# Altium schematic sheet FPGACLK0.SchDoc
size D; PageSetup: Record=PageOptions|CenterHorizontal=True|CenterVertical=True|PrintScale=1.12|XCorrection=1.00|YCorrection=1.00|PrintKind=0|BorderSize=5000000|LeftOffset=0|BottomOffset=0|Orientation=2|PaperLength=1000|PaperWidth=1000|Scale=100|PaperSource=7|PrintQuality=-4|MediaType=1|DitherType=10|PaperKind=Letter|PrintScaleMode=1
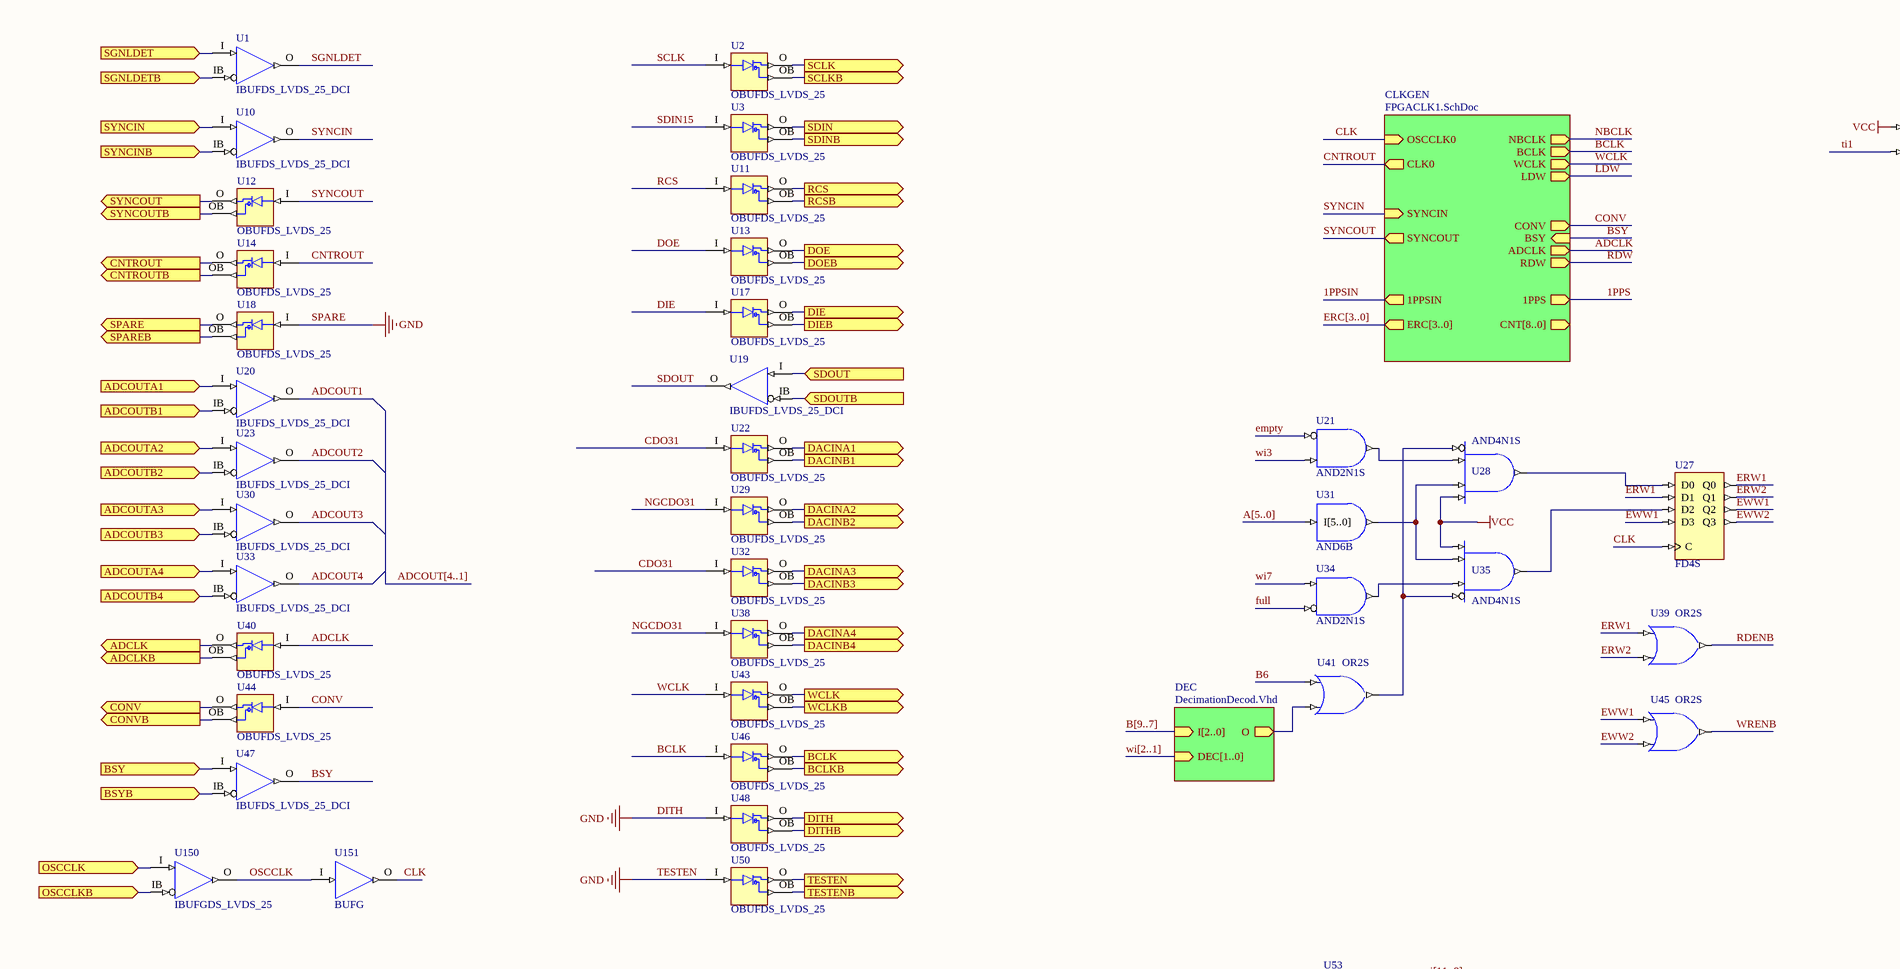
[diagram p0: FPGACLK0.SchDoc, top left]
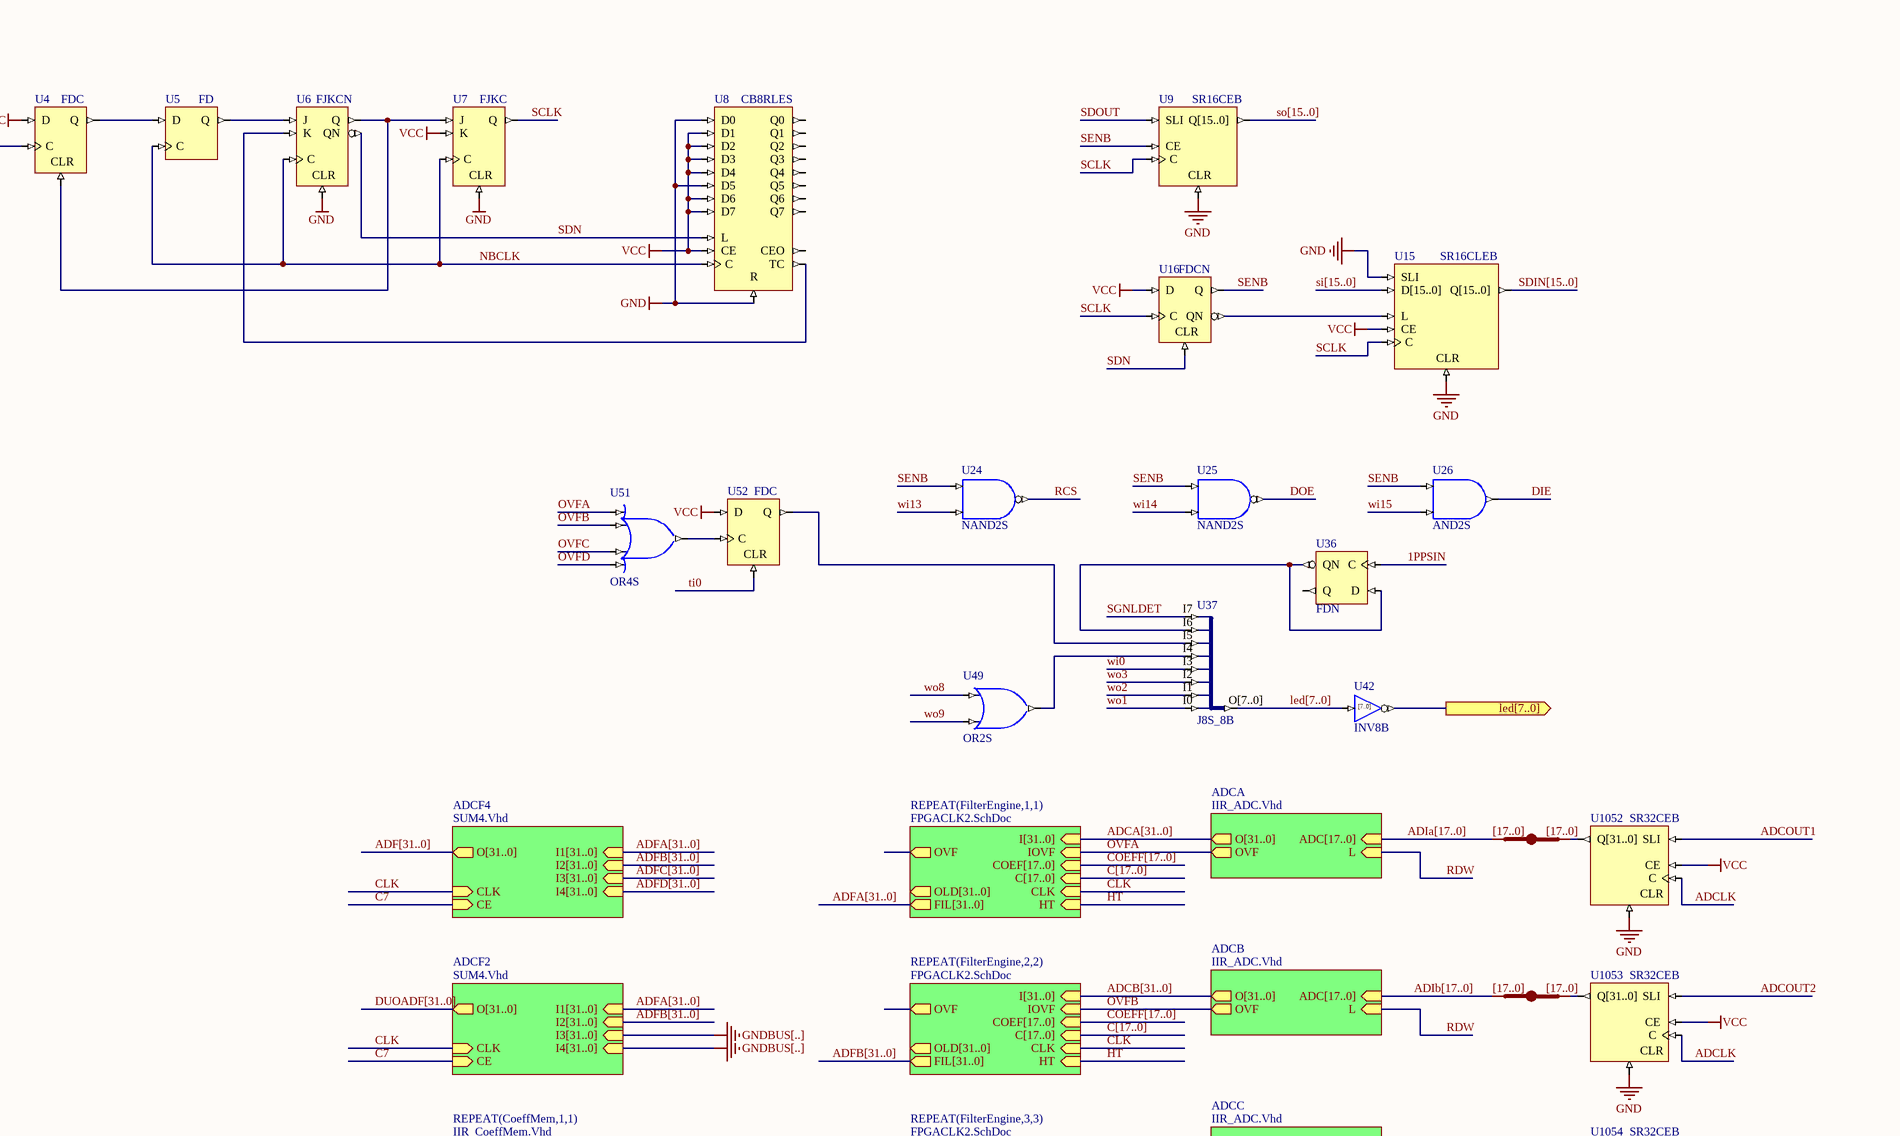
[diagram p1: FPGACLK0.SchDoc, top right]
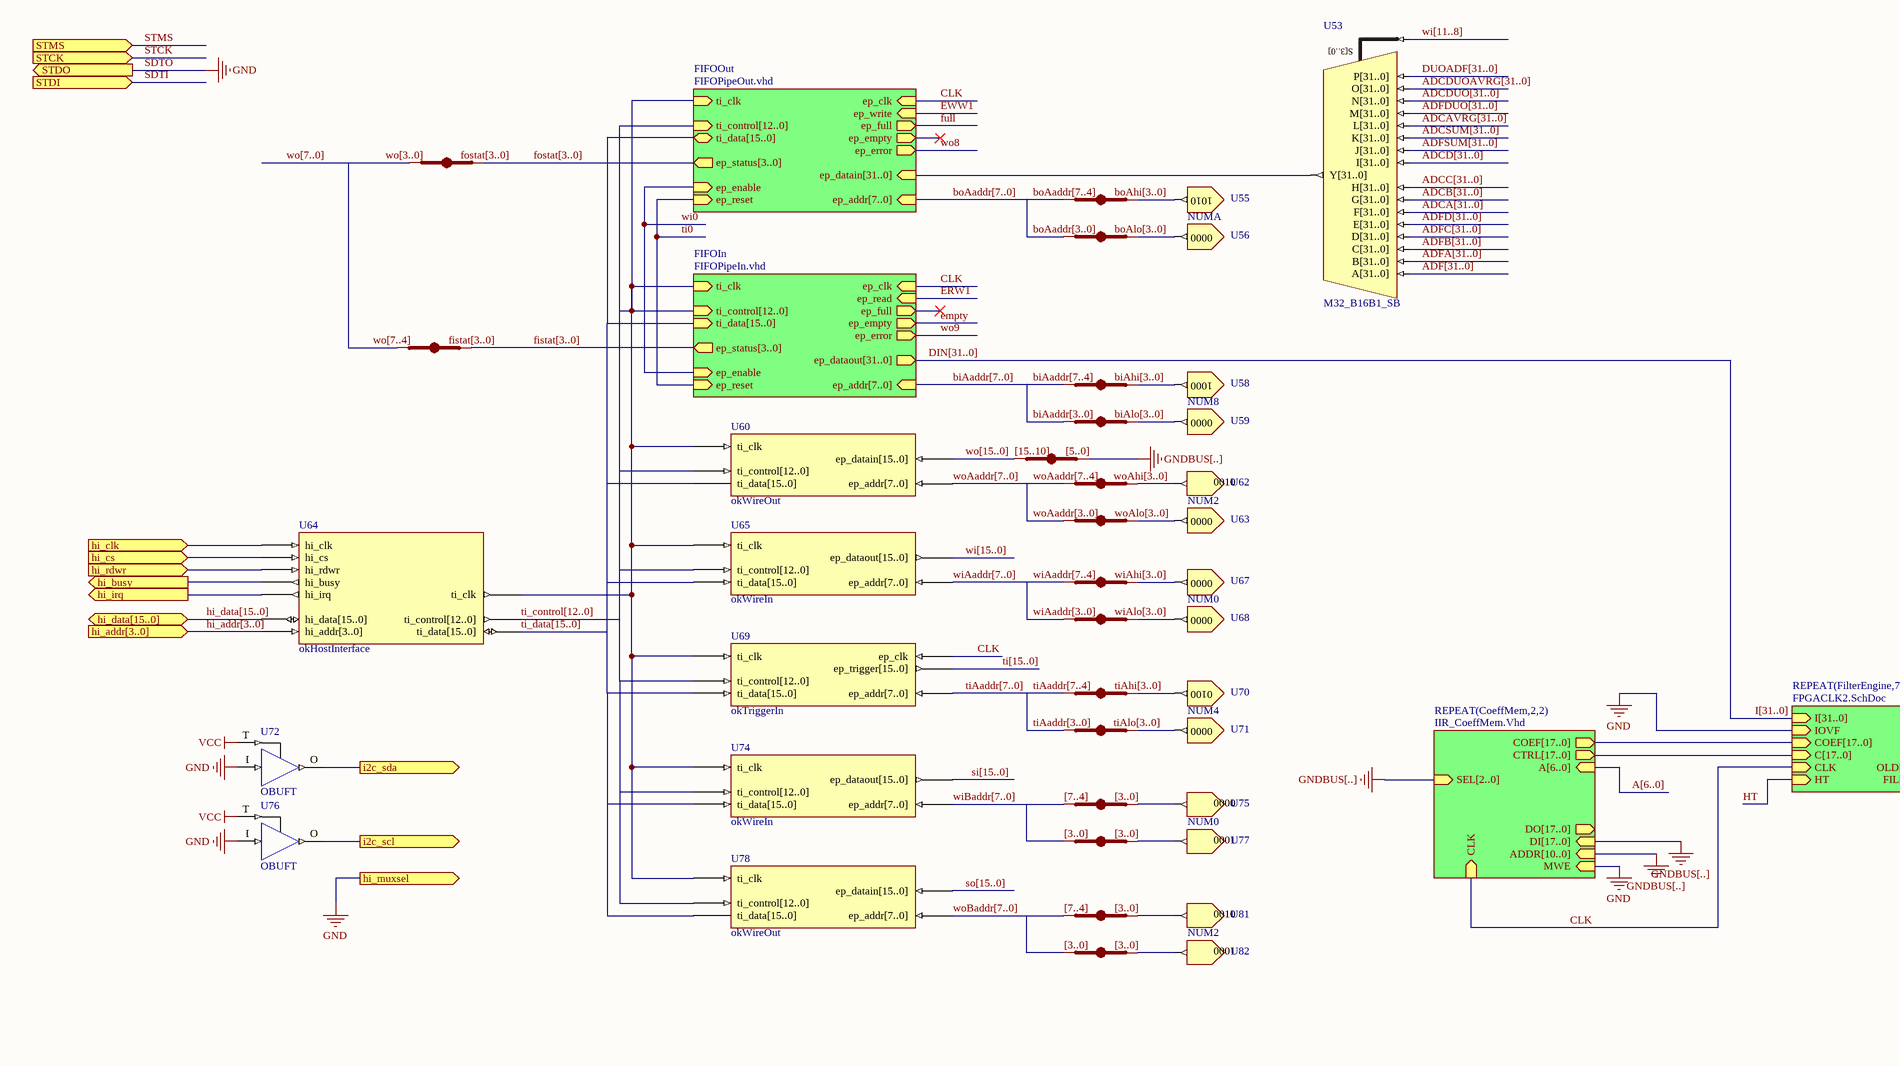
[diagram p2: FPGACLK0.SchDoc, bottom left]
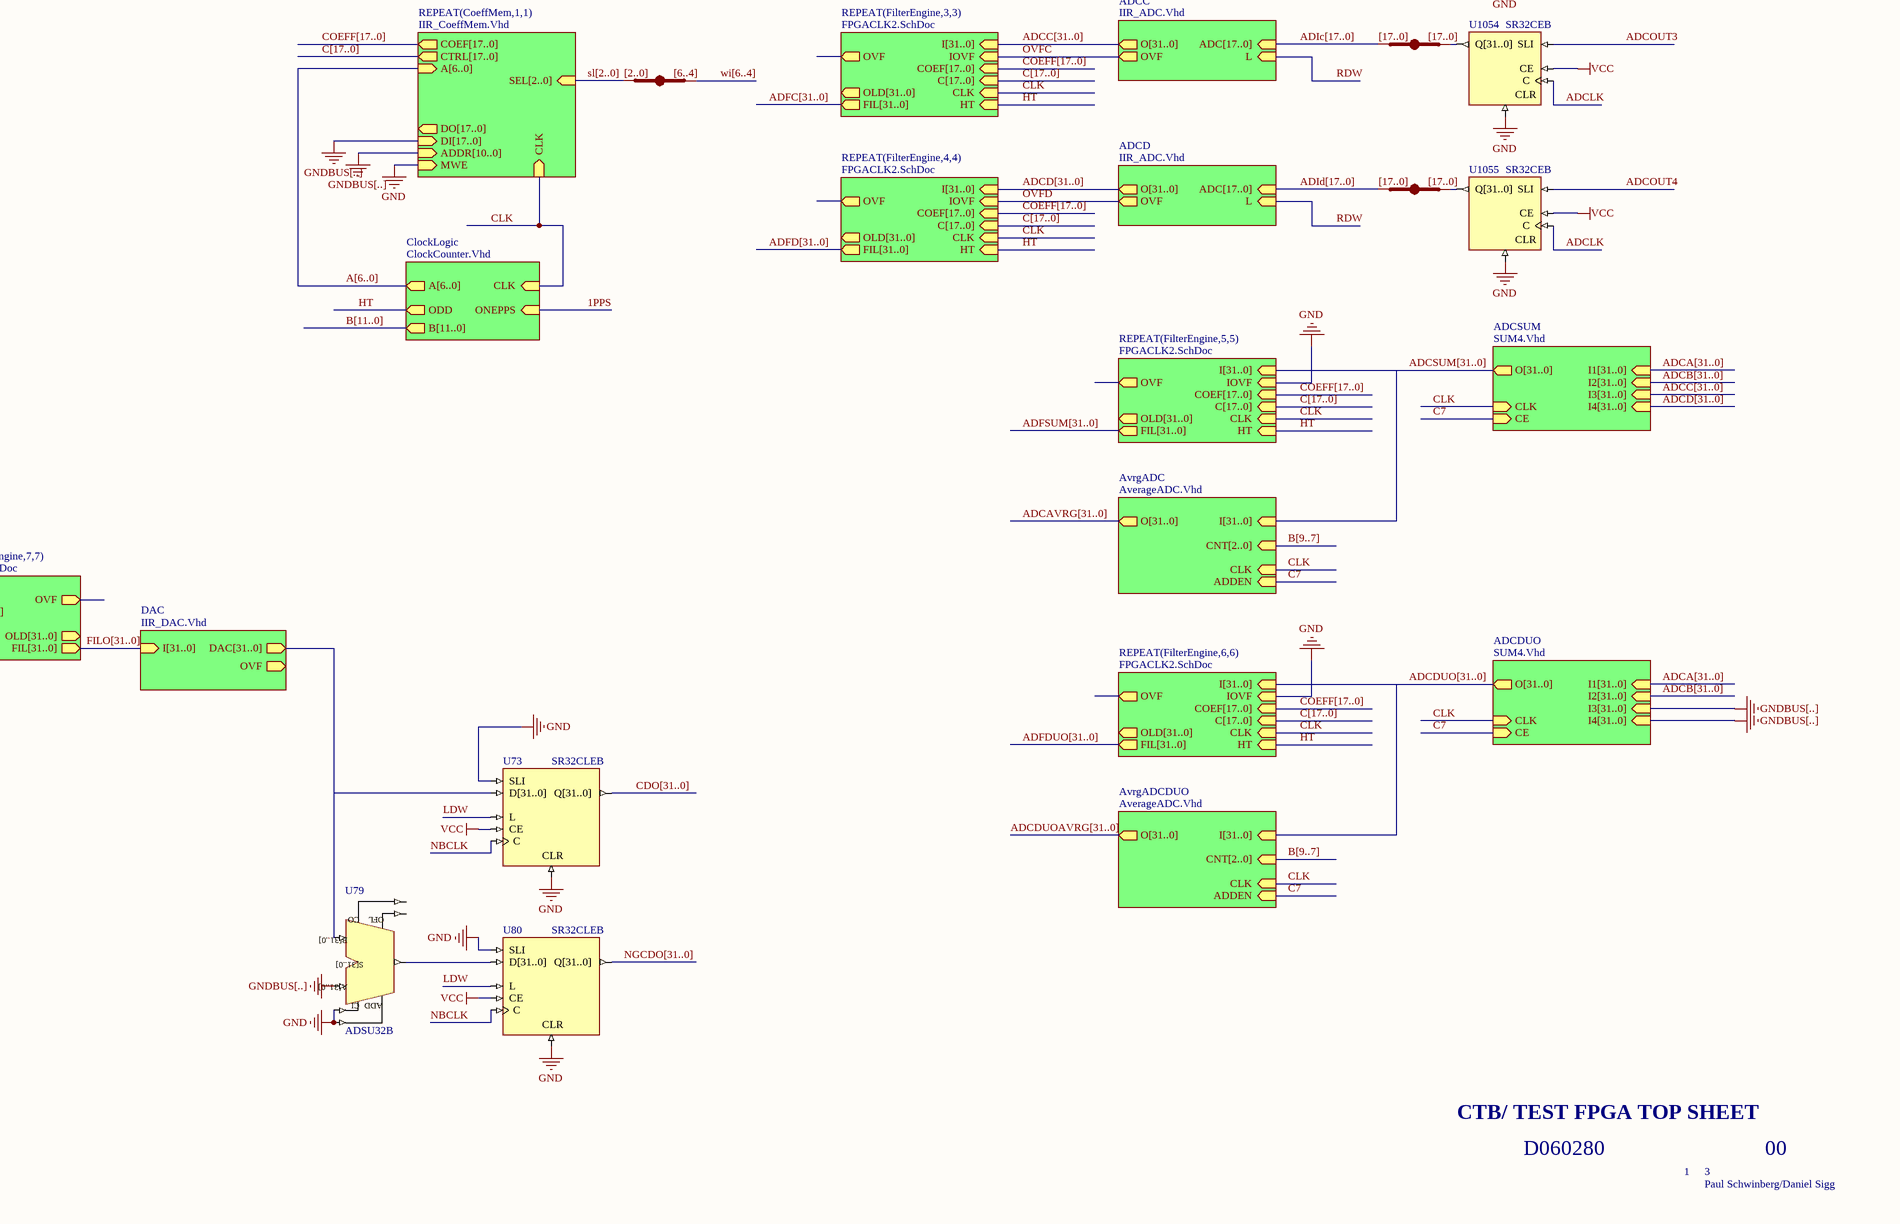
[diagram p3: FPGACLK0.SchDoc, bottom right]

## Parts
(Parts that share a designator on the sheet are numbered #1, #2 ... from top to bottom, then left to right.)
JB_C1#1  IndexA: [17..0]  (hidden comment: JB)
JB_C1#2  IndexA: [17..0]  (hidden comment: JB)
JB_C1#3  IndexA: [17..0]  (hidden comment: JB)
JB_C1#4  IndexA: [17..0]  (hidden comment: JB)
JB_C3  IndexA: wo[3..0]  IndexB: fostat[3..0]  (hidden comment: JB)
JB_C4  IndexA: boAaddr[7..4]  IndexB: boAhi[3..0]  (hidden comment: JB)
JB_C6  IndexA: [2..0]  IndexB: [6..4]  (hidden comment: JB)
JB_C7  IndexA: boAaddr[3..0]  IndexB: boAlo[3..0]  (hidden comment: JB)
JB_C9  IndexA: wo[7..4]  IndexB: fistat[3..0]  (hidden comment: JB)
JB_C10  IndexA: biAaddr[7..4]  IndexB: biAhi[3..0]  (hidden comment: JB)
JB_C11  IndexA: biAaddr[3..0]  IndexB: biAlo[3..0]  (hidden comment: JB)
JB_C12  IndexA: [15..10]  IndexB: [5..0]  (hidden comment: JB)
JB_C13  IndexA: woAaddr[7..4]  IndexB: woAhi[3..0]  (hidden comment: JB)
JB_C15  IndexA: woAaddr[3..0]  IndexB: woAlo[3..0]  (hidden comment: JB)
JB_C16  IndexA: wiAaddr[7..4]  IndexB: wiAhi[3..0]  (hidden comment: JB)
JB_C18  IndexA: wiAaddr[3..0]  IndexB: wiAlo[3..0]  (hidden comment: JB)
JB_C19  IndexA: tiAaddr[7..4]  IndexB: tiAhi[3..0]  (hidden comment: JB)
JB_C20  IndexA: tiAaddr[3..0]  IndexB: tiAlo[3..0]  (hidden comment: JB)
JB_C21  IndexA: [7..4]  IndexB: [3..0]  (hidden comment: JB)
JB_C22  IndexA: [3..0]  (hidden comment: JB)
JB_C23  IndexA: [7..4]  IndexB: [3..0]  (hidden comment: JB)
JB_C24  IndexA: [3..0]  (hidden comment: JB)
U1  IBUFDS_LVDS_25_DCI
U2  OBUFDS_LVDS_25
U3  OBUFDS_LVDS_25
U4  FDC
U5  FD
U6  FJKCN
U7  FJKC
U8  CB8RLES
U9  SR16CEB
U10  IBUFDS_LVDS_25_DCI
U11  OBUFDS_LVDS_25
U12  OBUFDS_LVDS_25
U13  OBUFDS_LVDS_25
U14  OBUFDS_LVDS_25
U15  SR16CLEB
U16  FDCN
U17  OBUFDS_LVDS_25
U18  OBUFDS_LVDS_25
U19  IBUFDS_LVDS_25_DCI
U20  IBUFDS_LVDS_25_DCI
U21  AND2N1S
U22  OBUFDS_LVDS_25
U23  IBUFDS_LVDS_25_DCI
U24  NAND2S
U25  NAND2S
U26  AND2S
U27  FD4S
U28  AND4N1S
U29  OBUFDS_LVDS_25
U30  IBUFDS_LVDS_25_DCI
U31  AND6B
U32  OBUFDS_LVDS_25
U33  IBUFDS_LVDS_25_DCI
U34  AND2N1S
U35  AND4N1S
U36  FDN
U37  J8S_8B
U38  OBUFDS_LVDS_25
U39  OR2S
U40  OBUFDS_LVDS_25
U41  OR2S
U42  INV8B
U43  OBUFDS_LVDS_25
U44  OBUFDS_LVDS_25
U45  OR2S
U46  OBUFDS_LVDS_25
U47  IBUFDS_LVDS_25_DCI
U48  OBUFDS_LVDS_25
U49  OR2S
U50  OBUFDS_LVDS_25
U51  OR4S
U52  FDC
U53  M32_B16B1_SB
U55  NUMA
U56  NUM0  (value not drawn)
U58  NUM8
U59  NUM0  (value not drawn)
U60  okWireOut
U62  NUM2
U63  NUM0  (value not drawn)
U64  okHostInterface
U65  okWireIn
U67  NUM0
U68  NUM0  (value not drawn)
U69  okTriggerIn
U70  NUM4
U71  NUM0  (value not drawn)
U72  OBUFT
U73  SR32CLEB
U74  okWireIn
U75  NUM0
U76  OBUFT
U77  NUM1  (value not drawn)
U78  okWireOut
U79  ADSU32B
U80  SR32CLEB
U81  NUM2
U82  NUM1  (value not drawn)
U150  IBUFGDS_LVDS_25
U151  BUFG
U1052  SR32CEB
U1053  SR32CEB
U1054  SR32CEB
U1055  SR32CEB

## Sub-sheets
ADCA = IIR_ADC.Vhd: ADC[17..0] (in), O[31..0] (out), L (in), OVF (out)
ADCB = IIR_ADC.Vhd: ADC[17..0] (in), O[31..0] (out), L (in), OVF (out)
ADCC = IIR_ADC.Vhd: ADC[17..0] (in), O[31..0] (out), L (in), OVF (out)
ADCD = IIR_ADC.Vhd: ADC[17..0] (in), O[31..0] (out), L (in), OVF (out)
ADCDUO = SUM4.Vhd: I1[31..0] (in), O[31..0] (out), I2[31..0] (in), I3[31..0] (in), I4[31..0] (in), CLK (in), CE (in)
ADCF2 = SUM4.Vhd: I1[31..0] (in), O[31..0] (out), I2[31..0] (in), I3[31..0] (in), I4[31..0] (in), CLK (in), CE (in)
ADCF4 = SUM4.Vhd: I1[31..0] (in), O[31..0] (out), I2[31..0] (in), I3[31..0] (in), I4[31..0] (in), CLK (in), CE (in)
ADCSUM = SUM4.Vhd: I1[31..0] (in), O[31..0] (out), I2[31..0] (in), I3[31..0] (in), I4[31..0] (in), CLK (in), CE (in)
AvrgADC = AverageADC.Vhd: I[31..0] (in), O[31..0] (out), ADDEN (in), CNT[2..0] (in), CLK (in)
AvrgADCDUO = AverageADC.Vhd: I[31..0] (in), O[31..0] (out), ADDEN (in), CNT[2..0] (in), CLK (in)
CLKGEN = FPGACLK1.SchDoc: SYNCIN (in), OSCCLK0 (in), CLK0 (out), SYNCOUT (out), BCLK (out), WCLK (out), LDW (out), CONV (out), BSY (in), ADCLK (out), RDW (out), NBCLK (out), 1PPS (out), 1PPSIN (out), ERC[3..0] (out), CNT[8..0] (out)
ClockLogic = ClockCounter.Vhd: CLK (in), ONEPPS (in), A[6..0] (out), ODD (out), B[11..0] (out)
DAC = IIR_DAC.Vhd: I[31..0] (in), DAC[31..0] (out), OVF (out)
DEC = DecimationDecod.Vhd: I[2..0] (in), O (out), DEC[1..0] (in)
FIFOIn = FIFOPipeIn.vhd: ti_clk (in), ti_control[12..0] (in), ti_data[15..0] (in), ep_status[3..0] (out), ep_reset (in), ep_clk (in), ep_read (in), ep_full (out), ep_empty (out), ep_error (out), ep_addr[7..0] (in), ep_dataout[31..0] (out), ep_enable (in)
FIFOOut = FIFOPipeOut.vhd: ti_clk (in), ti_control[12..0] (in), ti_data[15..0] (bidir), ep_status[3..0] (out), ep_reset (in), ep_clk (in), ep_write (in), ep_full (out), ep_empty (out), ep_error (out), ep_addr[7..0] (in), ep_datain[31..0] (in), ep_enable (in)
REPEAT(CoeffMem,1,1) = IIR_CoeffMem.Vhd: CLK (in), A[6..0] (in), COEF[17..0] (out), CTRL[17..0] (out), SEL[2..0] (in), DI[17..0] (in), DO[17..0] (out), MWE (in), ADDR[10..0] (in)
REPEAT(CoeffMem,2,2) = IIR_CoeffMem.Vhd: CLK (in), A[6..0] (in), COEF[17..0] (out), CTRL[17..0] (out), SEL[2..0] (in), DI[17..0] (in), DO[17..0] (out), MWE (in), ADDR[10..0] (in)
REPEAT(FilterEngine,1,1) = FPGACLK2.SchDoc: CLK (in), FIL[31..0] (out), I[31..0] (in), C[17..0] (in), COEF[17..0] (in), HT (in), OLD[31..0] (out), OVF (out), IOVF (in)
REPEAT(FilterEngine,2,2) = FPGACLK2.SchDoc: CLK (in), FIL[31..0] (out), I[31..0] (in), C[17..0] (in), COEF[17..0] (in), HT (in), OLD[31..0] (out), OVF (out), IOVF (in)
REPEAT(FilterEngine,3,3) = FPGACLK2.SchDoc: CLK (in), FIL[31..0] (out), I[31..0] (in), C[17..0] (in), COEF[17..0] (in), HT (in), OLD[31..0] (out), OVF (out), IOVF (in)
REPEAT(FilterEngine,4,4) = FPGACLK2.SchDoc: CLK (in), FIL[31..0] (out), I[31..0] (in), C[17..0] (in), COEF[17..0] (in), HT (in), OLD[31..0] (out), OVF (out), IOVF (in)
REPEAT(FilterEngine,5,5) = FPGACLK2.SchDoc: CLK (in), FIL[31..0] (out), I[31..0] (in), C[17..0] (in), COEF[17..0] (in), HT (in), OLD[31..0] (out), OVF (out), IOVF (in)
REPEAT(FilterEngine,6,6) = FPGACLK2.SchDoc: CLK (in), FIL[31..0] (out), I[31..0] (in), C[17..0] (in), COEF[17..0] (in), HT (in), OLD[31..0] (out), OVF (out), IOVF (in)
REPEAT(FilterEngine,7,7) = FPGACLK2.SchDoc: CLK (in), FIL[31..0] (out), I[31..0] (in), C[17..0] (in), COEF[17..0] (in), HT (in), OLD[31..0] (out), OVF (out), IOVF (in)

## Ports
ADCLK (out), ADCLKB (out), ADCOUTA1 (in), ADCOUTA2 (in), ADCOUTA3 (in), ADCOUTA4 (in), ADCOUTB1 (in), ADCOUTB2 (in), ADCOUTB3 (in), ADCOUTB4 (in), BCLK (out), BCLKB (out), BSY (in), BSYB (in), CNTROUT (out), CNTROUTB (out), CONV (out), CONVB (out), DACINA1 (out), DACINA2 (out), DACINA3 (out), DACINA4 (out), DACINB1 (out), DACINB2 (out), DACINB3 (out), DACINB4 (out), DIE (out), DIEB (out), DITH (out), DITHB (out), DOE (out), DOEB (out), hi_addr[3..0] (in), hi_busy (out), hi_clk (in), hi_cs (in), hi_data[15..0] (bidir), hi_irq (out), hi_muxsel (out), hi_rdwr (in), i2c_scl (out), i2c_sda (out), led[7..0] (out), OSCCLK (in), OSCCLKB (in), RCS (out), RCSB (out), SCLK (out), SCLKB (out), SDIN (out), SDINB (out), SDOUT (in), SDOUTB (in), SGNLDET (in), SGNLDETB (in), SPARE (out), SPAREB (out), STCK (in), STDI (in), STDO (out), STMS (in), SYNCIN (in), SYNCINB (in), SYNCOUT (out), SYNCOUTB (out), TESTEN (out), TESTENB (out), WCLK (out), WCLKB (out)

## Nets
DITH: U6.CLR U7.CLR U8.D0 U8.D5 U8.R U9.CLR U15.CLR U15.SLI U18.I U48.I U50.I U72.I U73.CLR U73.SLI U76.I U79.ADD U79.CI U80.CLR U80.SLI U1052.CLR U1053.CLR U1054.CLR U1055.CLR ; port hi_muxsel, port STDO, sheet REPEAT(CoeffMem,1,1)/MWE, sheet REPEAT(FilterEngine,7,7)/IOVF, sheet REPEAT(CoeffMem,2,2)/MWE, sheet REPEAT(FilterEngine,5,5)/IOVF, sheet REPEAT(FilterEngine,6,6)/IOVF  [also labelled GND, SDTO, SPARE, TESTEN]
GNDBUS[..]: U79.A[31..0]
VCC: U4.D U7.K U8.CE U8.D1 U8.D2 U8.D3 U8.D4 U8.D6 U8.D7 U15.CE U16.D U28.I3 U35.I3 U52.D U72.T U73.CE U76.T U80.CE U1052.CE U1053.CE U1054.CE U1055.CE
1PPS: sheet ClockLogic/ONEPPS, sheet CLKGEN/1PPS
1PPSIN: U36.C ; sheet CLKGEN/1PPSIN
ADCLK: U40.O ; port ADCLK
ADCLK: U40.I U1052.C U1053.C U1054.C U1055.C ; sheet CLKGEN/ADCLK  [a separate net that carries the same name]
ADCLKB: U40.OB ; port ADCLKB
ADCOUT1: U20.O U1052.SLI
ADCOUT2: U23.O U1053.SLI
ADCOUT3: U30.O U1054.SLI
ADCOUT4: U33.O U1055.SLI
ADCOUTA1: U20.I ; port ADCOUTA1
ADCOUTA2: U23.I ; port ADCOUTA2
ADCOUTA3: U30.I ; port ADCOUTA3
ADCOUTA4: U33.I ; port ADCOUTA4
ADCOUTB1: U20.IB ; port ADCOUTB1
ADCOUTB2: U23.IB ; port ADCOUTB2
ADCOUTB3: U30.IB ; port ADCOUTB3
ADCOUTB4: U33.IB ; port ADCOUTB4
B6: U41.I0
BCLK: U46.O ; port BCLK
BCLK: U46.I ; sheet CLKGEN/BCLK  [a separate net that carries the same name]
BCLKB: U46.OB ; port BCLKB
BSY: U47.O ; sheet CLKGEN/BSY
BSY: U47.I ; port BSY  [a separate net that carries the same name]
BSYB: U47.IB ; port BSYB
C7: sheet ADCF2/CE, sheet AvrgADC/ADDEN, sheet ADCSUM/CE, sheet AvrgADCDUO/ADDEN, sheet ADCDUO/CE, sheet ADCF4/CE
CDO31: U22.I U32.I
CLK: U27.C U69.ep_clk U151.O ; sheet ClockLogic/CLK, sheet REPEAT(CoeffMem,1,1)/CLK, sheet REPEAT(FilterEngine,7,7)/CLK, sheet REPEAT(CoeffMem,2,2)/CLK, sheet CLKGEN/OSCCLK0, sheet REPEAT(FilterEngine,1,1)/CLK, sheet REPEAT(FilterEngine,2,2)/CLK, sheet REPEAT(FilterEngine,3,3)/CLK, sheet REPEAT(FilterEngine,4,4)/CLK, sheet ADCF2/CLK, sheet AvrgADC/CLK, sheet ADCSUM/CLK, sheet REPEAT(FilterEngine,5,5)/CLK, sheet FIFOIn/ep_clk, sheet FIFOOut/ep_clk, sheet AvrgADCDUO/CLK, sheet ADCDUO/CLK, sheet REPEAT(FilterEngine,6,6)/CLK, sheet ADCF4/CLK
CNTROUT: U14.O ; port CNTROUT
CNTROUT: U14.I ; sheet CLKGEN/CLK0  [a separate net that carries the same name]
CNTROUTB: U14.OB ; port CNTROUTB
CONV: U44.O ; port CONV
CONV: U44.I ; sheet CLKGEN/CONV  [a separate net that carries the same name]
CONVB: U44.OB ; port CONVB
DACINA1: U22.O ; port DACINA1
DACINA2: U29.O ; port DACINA2
DACINA3: U32.O ; port DACINA3
DACINA4: U38.O ; port DACINA4
DACINB1: U22.OB ; port DACINB1
DACINB2: U29.OB ; port DACINB2
DACINB3: U32.OB ; port DACINB3
DACINB4: U38.OB ; port DACINB4
DIE: U17.O ; port DIE
DIE: U17.I U26.O  [a separate net that carries the same name]
DIEB: U17.OB ; port DIEB
DITH: U48.O ; port DITH  [a separate net that carries the same name]
DITHB: U48.OB ; port DITHB
DOE: U13.O ; port DOE
DOE: U13.I U25.O  [a separate net that carries the same name]
DOEB: U13.OB ; port DOEB
empty: U21.I0 ; sheet FIFOIn/ep_empty
ERW1: U27.D1 U27.Q0 U39.I0 ; sheet FIFOIn/ep_read
ERW2: U27.Q1 U39.I1
EWW1: U27.D3 U27.Q2 U45.I0 ; sheet FIFOOut/ep_write
EWW2: U27.Q3 U45.I1
full: U34.I0 ; sheet FIFOOut/ep_full
hi_busy: U64.hi_busy ; port hi_busy
hi_clk: U64.hi_clk ; port hi_clk
hi_cs: U64.hi_cs ; port hi_cs
hi_irq: U64.hi_irq ; port hi_irq
hi_rdwr: U64.hi_rdwr ; port hi_rdwr
HT: sheet ClockLogic/ODD, sheet REPEAT(FilterEngine,7,7)/HT, sheet REPEAT(FilterEngine,1,1)/HT, sheet REPEAT(FilterEngine,2,2)/HT, sheet REPEAT(FilterEngine,3,3)/HT, sheet REPEAT(FilterEngine,4,4)/HT, sheet REPEAT(FilterEngine,5,5)/HT, sheet REPEAT(FilterEngine,6,6)/HT
i2c_scl: U76.O ; port i2c_scl
i2c_sda: U72.O ; port i2c_sda
LDW: U73.L U80.L ; sheet CLKGEN/LDW
NBCLK: U5.C U6.C U7.C U8.C U73.C U80.C ; sheet CLKGEN/NBCLK
NGCDO31: U29.I U38.I
OSCCLK: U150.O U151.I
OSCCLK: U150.I ; port OSCCLK  [a separate net that carries the same name]
OSCCLKB: U150.IB ; port OSCCLKB
OVFA: U51.I0 ; sheet ADCA/OVF, sheet REPEAT(FilterEngine,1,1)/IOVF
OVFB: U51.I1 ; sheet ADCB/OVF, sheet REPEAT(FilterEngine,2,2)/IOVF
OVFC: U51.I2 ; sheet ADCC/OVF, sheet REPEAT(FilterEngine,3,3)/IOVF
OVFD: U51.I3 ; sheet ADCD/OVF, sheet REPEAT(FilterEngine,4,4)/IOVF
RCS: U11.O ; port RCS
RCS: U11.I U24.O  [a separate net that carries the same name]
RCSB: U11.OB ; port RCSB
RDENB: U39.O
RDW: sheet CLKGEN/RDW, sheet ADCC/L, sheet ADCD/L, sheet ADCB/L, sheet ADCA/L
SCLK: U2.O ; port SCLK
SCLK: U2.I U7.Q U9.C U15.C U16.C  [a separate net that carries the same name]
SCLKB: U2.OB ; port SCLKB
SDIN: U3.O ; port SDIN
SDIN15: U3.I
SDINB: U3.OB ; port SDINB
SDN: U6.QN U8.L U16.CLR
SDOUT: U9.SLI U19.O
SDOUT: U19.I ; port SDOUT  [a separate net that carries the same name]
SDOUTB: U19.IB ; port SDOUTB
SENB: U9.CE U16.Q U24.I0 U25.I0 U26.I0
SGNLDET: U1.O U37.I7
SGNLDET: U1.I ; port SGNLDET  [a separate net that carries the same name]
SGNLDETB: U1.IB ; port SGNLDETB
SPARE: U18.O ; port SPARE
SPAREB: U18.OB ; port SPAREB
SYNCIN: U10.O ; sheet CLKGEN/SYNCIN
SYNCIN: U10.I ; port SYNCIN  [a separate net that carries the same name]
SYNCINB: U10.IB ; port SYNCINB
SYNCOUT: U12.O ; port SYNCOUT
SYNCOUT: U12.I ; sheet CLKGEN/SYNCOUT  [a separate net that carries the same name]
SYNCOUTB: U12.OB ; port SYNCOUTB
TESTEN: U50.O ; port TESTEN
TESTENB: U50.OB ; port TESTENB
ti0: U52.CLR ; sheet FIFOIn/ep_reset, sheet FIFOOut/ep_reset
ti1: U4.C
WCLK: U43.O ; port WCLK
WCLK: U43.I ; sheet CLKGEN/WCLK  [a separate net that carries the same name]
WCLKB: U43.OB ; port WCLKB
wi0: U37.I3 ; sheet FIFOIn/ep_enable, sheet FIFOOut/ep_enable
wi3: U21.I1
wi7: U34.I1
wi13: U24.I1
wi14: U25.I1
wi15: U26.I1
wo1: U37.I0
wo2: U37.I1
wo3: U37.I2
wo8: U49.I0 ; sheet FIFOOut/ep_error
wo9: U49.I1 ; sheet FIFOIn/ep_error
WRENB: U45.O
NetU4_CLR: U4.CLR U6.Q U7.J
NetU4_Q: U4.Q U5.D
NetU5_Q: U5.Q U6.J
NetU6_K: U6.K U8.TC
NetU15_L: U15.L U16.QN
NetU21_O: U21.O U28.I1
NetU27_D0: U27.D0 U28.O
NetU27_D2: U27.D2 U35.O
NetU28_I0: U28.I0 U35.I0 U41.O
NetU28_I2: U28.I2 U31.O U35.I2
NetU34_O: U34.O U35.I1
NetU36_D: U36.D U36.QN U37.I6
NetU37_I4: U37.I4 U49.O
NetU37_I5: U37.I5 U52.Q
NetU41_I1: U41.I1 ; sheet DEC/O
NetU51_O: U51.O U52.C
NetU60_ti_clk: U60.ti_clk U64.ti_clk U65.ti_clk U69.ti_clk U74.ti_clk U78.ti_clk ; sheet FIFOIn/ti_clk, sheet FIFOOut/ti_clk

Not connected (* = marked no-connect by the designer): JB_C1#1 A[0..0] B[0..0]; JB_C1#2 A[0..0] B[0..0]; JB_C1#3 A[0..0] B[0..0]; JB_C1#4 A[0..0] B[0..0]; JB_C3 A[0..0] B[0..0]; JB_C4 A[0..0] B[0..0]; JB_C6 A[0..0] B[0..0]; JB_C7 A[0..0] B[0..0]; JB_C9 A[0..0] B[0..0]; JB_C10 A[0..0] B[0..0]; JB_C11 A[0..0] B[0..0]; JB_C12 A[0..0] B[0..0]; JB_C13 A[0..0] B[0..0]; JB_C15 A[0..0] B[0..0]; JB_C16 A[0..0] B[0..0]; JB_C18 A[0..0] B[0..0]; JB_C19 A[0..0] B[0..0]; JB_C20 A[0..0] B[0..0]; JB_C21 A[0..0] B[0..0]; JB_C22 A[0..0] B[0..0]; JB_C23 A[0..0] B[0..0]; JB_C24 A[0..0] B[0..0]; U8 CEO Q0 Q1 Q2 Q3 Q4 Q5 Q6 Q7; U9 Q[15..0]; U15 D[15..0] Q[15..0]; U31 I[5..0]; U36 Q; U37 O[7..0]; U42 I[7..0] O[7..0]; U53 A[31..0] B[31..0] C[31..0] D[31..0] E[31..0] F[31..0] G[31..0] H[31..0] I[31..0] J[31..0] K[31..0] L[31..0] M[31..0] N[31..0] O[31..0] P[31..0] S[3..0] Y[31..0]; U55 O[3..0]; U56 O[3..0]; U58 O[3..0]; U59 O[3..0]; U60 ep_addr[7..0] ep_datain[15..0] ti_control[12..0] ti_data[15..0]; U62 O[3..0]; U63 O[3..0]; U64 hi_addr[3..0] hi_data[15..0] ti_control[12..0] ti_data[15..0]; U65 ep_addr[7..0] ep_dataout[15..0] ti_control[12..0] ti_data[15..0]; U67 O[3..0]; U68 O[3..0]; U69 ep_addr[7..0] ep_trigger[15..0] ti_control[12..0] ti_data[15..0]; U70 O[3..0]; U71 O[3..0]; U73 D[31..0] Q[31..0]; U74 ep_addr[7..0] ep_dataout[15..0] ti_control[12..0] ti_data[15..0]; U75 O[3..0]; U77 O[3..0]; U78 ep_addr[7..0] ep_datain[15..0] ti_control[12..0] ti_data[15..0]; U79 B[31..0] CO OFL S[31..0]; U80 D[31..0] Q[31..0]; U81 O[3..0]; U82 O[3..0]; U1052 Q[31..0]; U1053 Q[31..0]; U1054 Q[31..0]; U1055 Q[31..0]

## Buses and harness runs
bus A[5..0]
bus A[6..0] = sheet ClockLogic/A[6..0] = sheet REPEAT(CoeffMem,1,1)/A[6..0]
bus A[6..0] = sheet REPEAT(CoeffMem,2,2)/A[6..0]
bus ADCA[31..0]
bus ADCA[31..0] = sheet ADCA/O[31..0] = sheet REPEAT(FilterEngine,1,1)/I[31..0]
bus ADCA[31..0] = sheet ADCDUO/I1[31..0]
bus ADCA[31..0] = sheet ADCSUM/I1[31..0]
bus ADCAVRG[31..0]
bus ADCAVRG[31..0] = sheet AvrgADC/O[31..0]
bus ADCB[31..0]
bus ADCB[31..0] = sheet ADCB/O[31..0] = sheet REPEAT(FilterEngine,2,2)/I[31..0]
bus ADCB[31..0] = sheet ADCDUO/I2[31..0]
bus ADCB[31..0] = sheet ADCSUM/I2[31..0]
bus ADCC[31..0]
bus ADCC[31..0] = sheet ADCC/O[31..0] = sheet REPEAT(FilterEngine,3,3)/I[31..0]
bus ADCC[31..0] = sheet ADCSUM/I3[31..0]
bus ADCD[31..0]
bus ADCD[31..0] = sheet ADCD/O[31..0] = sheet REPEAT(FilterEngine,4,4)/I[31..0]
bus ADCD[31..0] = sheet ADCSUM/I4[31..0]
bus ADCDUO[31..0]
bus ADCDUO[31..0] = sheet ADCDUO/O[31..0] = sheet AvrgADCDUO/I[31..0] = sheet REPEAT(FilterEngine,6,6)/I[31..0]
bus ADCDUOAVRG[31..0]
bus ADCDUOAVRG[31..0] = sheet AvrgADCDUO/O[31..0]
bus ADCOUT[4..1]
bus ADCSUM[31..0]
bus ADCSUM[31..0] = sheet ADCSUM/O[31..0] = sheet AvrgADC/I[31..0] = sheet REPEAT(FilterEngine,5,5)/I[31..0]
bus ADF[31..0]
bus ADF[31..0] = sheet ADCF4/O[31..0]
bus ADFA[31..0]
bus ADFA[31..0] = sheet ADCF2/I1[31..0]
bus ADFA[31..0] = sheet ADCF4/I1[31..0]
bus ADFA[31..0] = sheet REPEAT(FilterEngine,1,1)/FIL[31..0]
bus ADFB[31..0]
bus ADFB[31..0] = sheet ADCF2/I2[31..0]
bus ADFB[31..0] = sheet ADCF4/I2[31..0]
bus ADFB[31..0] = sheet REPEAT(FilterEngine,2,2)/FIL[31..0]
bus ADFC[31..0]
bus ADFC[31..0] = sheet ADCF4/I3[31..0]
bus ADFC[31..0] = sheet REPEAT(FilterEngine,3,3)/FIL[31..0]
bus ADFD[31..0]
bus ADFD[31..0] = sheet ADCF4/I4[31..0]
bus ADFD[31..0] = sheet REPEAT(FilterEngine,4,4)/FIL[31..0]
bus ADFDUO[31..0]
bus ADFDUO[31..0] = sheet REPEAT(FilterEngine,6,6)/FIL[31..0]
bus ADFSUM[31..0]
bus ADFSUM[31..0] = sheet REPEAT(FilterEngine,5,5)/FIL[31..0]
bus ADIa[17..0] = sheet ADCA/ADC[17..0]
bus ADIb[17..0] = sheet ADCB/ADC[17..0]
bus ADIc[17..0] = sheet ADCC/ADC[17..0]
bus ADId[17..0] = sheet ADCD/ADC[17..0]
bus B[9..7] = sheet AvrgADC/CNT[2..0]
bus B[9..7] = sheet AvrgADCDUO/CNT[2..0]
bus B[9..7] = sheet DEC/I[2..0]
bus B[11..0] = sheet ClockLogic/B[11..0]
bus biAaddr[7..0] = sheet FIFOIn/ep_addr[7..0]
bus boAaddr[7..0] = sheet FIFOOut/ep_addr[7..0]
bus C[17..0] = sheet REPEAT(CoeffMem,1,1)/CTRL[17..0]
bus C[17..0] = sheet REPEAT(FilterEngine,1,1)/C[17..0]
bus C[17..0] = sheet REPEAT(FilterEngine,2,2)/C[17..0]
bus C[17..0] = sheet REPEAT(FilterEngine,3,3)/C[17..0]
bus C[17..0] = sheet REPEAT(FilterEngine,4,4)/C[17..0]
bus C[17..0] = sheet REPEAT(FilterEngine,5,5)/C[17..0]
bus C[17..0] = sheet REPEAT(FilterEngine,6,6)/C[17..0]
bus CDO[31..0]
bus COEFF[17..0] = sheet REPEAT(CoeffMem,1,1)/COEF[17..0]
bus COEFF[17..0] = sheet REPEAT(FilterEngine,1,1)/COEF[17..0]
bus COEFF[17..0] = sheet REPEAT(FilterEngine,2,2)/COEF[17..0]
bus COEFF[17..0] = sheet REPEAT(FilterEngine,3,3)/COEF[17..0]
bus COEFF[17..0] = sheet REPEAT(FilterEngine,4,4)/COEF[17..0]
bus COEFF[17..0] = sheet REPEAT(FilterEngine,5,5)/COEF[17..0]
bus COEFF[17..0] = sheet REPEAT(FilterEngine,6,6)/COEF[17..0]
bus DIN[31..0] = I[31..0] = sheet FIFOIn/ep_dataout[31..0] = sheet REPEAT(FilterEngine,7,7)/I[31..0]
bus DUOADF[31..0]
bus DUOADF[31..0] = sheet ADCF2/O[31..0]
bus ERC[3..0] = sheet CLKGEN/ERC[3..0]
bus FILO[31..0] = sheet DAC/I[31..0] = sheet REPEAT(FilterEngine,7,7)/FIL[31..0]
bus fistat[3..0] = sheet FIFOIn/ep_status[3..0]
bus fostat[3..0] = sheet FIFOOut/ep_status[3..0]
bus hi_addr[3..0] = port hi_addr[3..0]
bus hi_data[15..0] = port hi_data[15..0]
bus led[7..0]
bus NGCDO[31..0]
bus SDIN[15..0]
bus sheet REPEAT(CoeffMem,2,2)/COEF[17..0] = sheet REPEAT(FilterEngine,7,7)/COEF[17..0]
bus sheet REPEAT(CoeffMem,2,2)/CTRL[17..0] = sheet REPEAT(FilterEngine,7,7)/C[17..0]
bus si[15..0]
bus sl[2..0] = sheet REPEAT(CoeffMem,1,1)/SEL[2..0]
bus so[15..0]
bus ti[15..0]
bus ti_control[12..0] = sheet FIFOIn/ti_control[12..0] = sheet FIFOOut/ti_control[12..0]
bus ti_data[15..0] = sheet FIFOIn/ti_data[15..0] = sheet FIFOOut/ti_data[15..0]
bus tiAaddr[7..0]
bus wi[2..1] = sheet DEC/DEC[1..0]
bus wi[6..4]
bus wi[11..8]
bus wi[15..0]
bus wiAaddr[7..0]
bus wiBaddr[7..0]
bus wo[7..0]
bus wo[15..0]
bus woAaddr[7..0]
bus woBaddr[7..0]

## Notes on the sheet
- CTB/ TEST FPGA TOP SHEET
- D060280
- 1
- Paul Schwinberg/Daniel Sigg
- 3
- 00
- Labels drawn without touching a wire or pin: GNDBUS[..]

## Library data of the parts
JB_C1#1-JB_C1#4 JB_C3 JB_C4 JB_C6 JB_C7 JB_C9-JB_C13 JB_C15 JB_C16 JB_C18-JB_C24 = JB: System BUS Joiner
U1 U10 U19 U20 U23 U30 U33 U47 = IBUFDS_LVDS_25_DCI: Differential Signaling Input Buffer with LVDS_25_DCI I/O Interface; FPGAVendor: Xilinx
U2 U3 U11-U14 U17 U18 U22 U29 U32 U38 U40 U43 U44 U46 U48 U50 = OBUFDS_LVDS_25: Differential Signaling Output Buffer with LVDS_25 I/O Interface; FPGAVendor: Xilinx
U4 U52 = FDC: D-Type Flip-Flop with Asynchronous Clear; SubClass: FD; ClockTrigger: Rising; ArchiveName: GENERIC; VHDLIB_SIM: GENERIC_LIB
U5 = FD: D-Type Flip-Flop; ClockTrigger: Rising; ArchiveName: GENERIC; VHDLIB_SIM: GENERIC_LIB
U6 = FJKCN: J-K Flip-Flop with Asynchronous Clear and Inverted and Non-Inverted Outputs; SubClass: JK; ClockTrigger: Rising; ArchiveName: GENERIC; VHDLIB_SIM: GENERIC_LIB
U7 = FJKC: J-K Flip-Flop with Asynchronous Clear; SubClass: JK; ClockTrigger: Rising; ArchiveName: GENERIC; VHDLIB_SIM: GENERIC_LIB
U8 = CB8RLES: 8-Bit Loadable Cascadable Binary Counter with Clock Enable and Synchronous Reset, Single Pin Version; ClockTrigger: Rising; Enable: High; Loadable: True; PortSize: 8; ArchiveName: GENERIC; VHDLIB_SIM: GENERIC_LIB
U9 = SR16CEB: 16-Bit Serial-In Parallel-Out Shift Registers with Clock Enable and Asynchronous Clear, Bus Version; XilinxEquivalent: SR16CE; ClockTrigger: Rising; Enable: High; PortSize: 16; ArchiveName: GENERIC; VHDLIB_SIM: GENERIC_LIB
U15 = SR16CLEB: 16-Bit Loadable Serial/Parallel-In Parallel-Out Shift Registers with Clock Enable and Asynchronous Clear, Bus Version; ClockTrigger: Rising; Enable: High; Loadable: True; PortSize: 16; ArchiveName: GENERIC; VHDLIB_SIM: GENERIC_LIB
U16 = FDCN: D-Type Flip-Flop with Asynchronous Clear and Inverted and Non-Inverted Outputs; SubClass: FD; ClockTrigger: Rising; ArchiveName: GENERIC; VHDLIB_SIM: GENERIC_LIB
U21 U34 = AND2N1S: 2-Input AND Gate with Active Low A Input, Single Pin Version; XilinxEquivalent: AND2B1; FunctionalClass: Logic Primitive; PortSize: 2; ArchiveName: GENERIC; VHDLIB_SIM: GENERIC_LIB
U24 U25 = NAND2S: 2-Input NAND Gate, Single Pin Version; XilinxEquivalent: NAND2; FunctionalClass: Logic Primitive; PortSize: 2; ArchiveName: GENERIC; VHDLIB_SIM: GENERIC_LIB
U26 = AND2S: 2-Input AND Gate, Single Pin Version; XilinxEquivalent: AND2; FunctionalClass: Logic Primitive; PortSize: 2; ArchiveName: GENERIC; VHDLIB_SIM: GENERIC_LIB
U27 = FD4S: 4-Bit D-Type Flip-Flop, Single Pin Version; XilinxEquivalent: FD4; SubClass: FD; ClockTrigger: Rising; PortSize: 4; ArchiveName: GENERIC; VHDLIB_SIM: GENERIC_LIB
U28 U35 = AND4N1S: 4-Input AND Gate with Active Low A Input, Single Pin Version; XilinxEquivalent: AND4B1; FunctionalClass: Logic Primitive; PortSize: 4; ArchiveName: GENERIC; VHDLIB_SIM: GENERIC_LIB
U31 = AND6B: 6-Input AND Gate, Bus Version; FunctionalClass: Logic Primitive; PortSize: 6; ArchiveName: GENERIC; VHDLIB_SIM: GENERIC_LIB
U36 = FDN: D-Type Flip-Flop with Inverted and Non-Inverted Outputs; SubClass: FD; ClockTrigger: Rising; ArchiveName: GENERIC; VHDLIB_SIM: GENERIC_LIB
U37 = J8S_8B: 8 Single pin inputs to single 8-Bit output bus; FunctionalClass: Bus Joiner; PortSize: 8; ArchiveName: GENERIC; VHDLIB_SIM: GENERIC_LIB
U39 U41 U45 U49 = OR2S: 2-Input OR Gate, Single Pin Version; XilinxEquivalent: OR2; FunctionalClass: Logic Primitive; PortSize: 2; ArchiveName: GENERIC; VHDLIB_SIM: GENERIC_LIB
U42 = INV8B: 8-Bit Inverter, Bus Version; XilinxEquivalent: INV8; FunctionalClass: Logic Primitive; SubClass: INV; PortSize: 8; ArchiveName: GENERIC; VHDLIB_SIM: GENERIC_LIB
U51 = OR4S: 4-Input OR Gate, Single Pin Version; XilinxEquivalent: OR4; FunctionalClass: Logic Primitive; PortSize: 4; ArchiveName: GENERIC; VHDLIB_SIM: GENERIC_LIB
U53 = M32_B16B1_SB: 16x32-Bit Bus to 1x32-Bit Bus Multiplexer With Bus Version Select; SubClass: BnB1; BusBusSelect: True; PortSize: 32; ArchiveName: GENERIC; VHDLIB_SIM: GENERIC_LIB
U55 = NUMA: Number Connector A; FunctionalClass: Numeric Connector; PortSize: 4; PortStyle: Bus Version; ArchiveName: GENERIC; VHDLIB_SIM: GENERIC_LIB
U56 U59 U63 U67 U68 U71 U75 = NUM0: Number Connector 0; FunctionalClass: Numeric Connector; SubClass: 0; PortSize: 4; PortStyle: Bus Version; ArchiveName: GENERIC; VHDLIB_SIM: GENERIC_LIB
U58 = NUM8: Number Connector 8; FunctionalClass: Numeric Connector; SubClass: 8; PortSize: 4; PortStyle: Bus Version; ArchiveName: GENERIC; VHDLIB_SIM: GENERIC_LIB
U60 U78 = okWireOut: Opal Kelly FPGA Board Wire Output Interface
U62 U81 = NUM2: Number Connector 2; FunctionalClass: Numeric Connector; SubClass: 2; PortSize: 4; PortStyle: Bus Version; ArchiveName: GENERIC; VHDLIB_SIM: GENERIC_LIB
U64 = okHostInterface: Opal Kelly FPGA Board Host Interface
U65 U74 = okWireIn: Opal Kelly FPGA Board Wire Input Interface
U69 = okTriggerIn: Opal Kelly FPGA Board Trigger Input Interface
U70 = NUM4: Number Connector 4; FunctionalClass: Numeric Connector; SubClass: 4; PortStyle: Bus Version; ArchiveName: GENERIC; VHDLIB_SIM: GENERIC_LIB
U72 U76 = OBUFT: Single 3-State Output Buffer with Active-Low Output Enable; FPGAVendor: Xilinx
U73 U80 = SR32CLEB: 32-Bit Loadable Serial/Parallel-In Parallel-Out Shift Registers with Clock Enable and Asynchronous Clear, Bus Version; ClockTrigger: Rising; Enable: High; Loadable: True; PortSize: 32; ArchiveName: GENERIC; VHDLIB_SIM: GENERIC_LIB
U77 U82 = NUM1: Number Connector 1; FunctionalClass: Numeric Connector; SubClass: 1; PortSize: 4; PortStyle: Bus Version; ArchiveName: GENERIC; VHDLIB_SIM: GENERIC_LIB
U79 = ADSU32B: 32-Bit Cascadable Full Adder/Subtracter with Signed and Unsigned Operations, Bus Version; FunctionalClass: Arithmetic Function; SubClass: ADSU; PortSize: 32; ArchiveName: GENERIC; VHDLIB_SIM: GENERIC_LIB
U150 = IBUFGDS_LVDS_25: Dedicated Differential Signaling Input Buffer with LVDS_25 I/O Interface; FPGAVendor: Xilinx
U151 = BUFG: Global Clock Buffer; FPGAVendor: Xilinx
U1052-U1055 = SR32CEB: 32-Bit Serial-In Parallel-Out Shift Registers with Clock Enable and Asynchronous Clear, Bus Version; ClockTrigger: Rising; Enable: High; PortSize: 32; ArchiveName: GENERIC; VHDLIB_SIM: GENERIC_LIB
